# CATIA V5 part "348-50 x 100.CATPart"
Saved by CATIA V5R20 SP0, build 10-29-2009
Part number: 348-50 x 100
Definition: NONE
Nomenclature: 348-50 x 100
Source: Unknown
Description: 348-50 x 100
Bounding box of the stored display mesh (mm): x 0 to 100, y -35 to 35, z -35 to 35
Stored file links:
  C:\Users\Utente\Desktop\IO LAVORO\3D X SITO CF\X SITO\3D files 348\348-50 x 100.CATPart
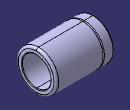
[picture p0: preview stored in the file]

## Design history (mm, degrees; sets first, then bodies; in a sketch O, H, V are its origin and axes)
Body1 "348-50 x 100" (main body)
  Solid1: solid without history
